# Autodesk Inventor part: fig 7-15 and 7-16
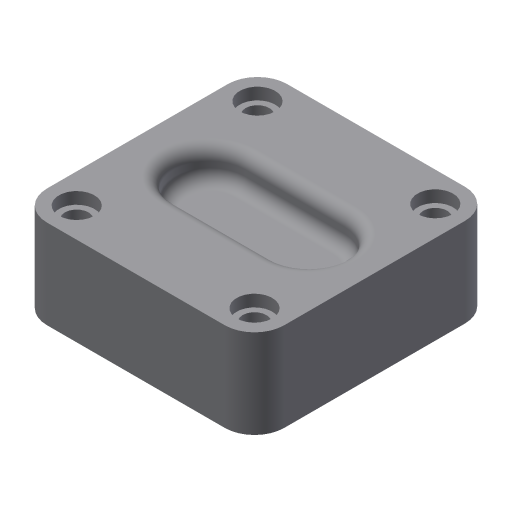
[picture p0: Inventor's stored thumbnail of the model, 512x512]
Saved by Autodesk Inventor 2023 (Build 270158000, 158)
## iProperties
Created: 2001-12
Part Number: fig 7-15 and 7-16
Document SubType Name: Modeling
Designer: Renu Muthoo
Density: 1 g/cm^3
Material: Generic
Appearance: Default
Control State: 0
Master: False
Checked Out: False
Shininess: 77.0
Angle Display Precision: 2
Document Length Units: 11269
Document Angle Units: 11279
Document Time Units: 11290
Document Mass Units: 11283
Document Length Units Precision: 3
Document Angle Units Precision: 2
Density: 0.0
Volumn: 0.0
Area: 0.0
PropertySet Name: Model Information
Author: Renu Muthoo
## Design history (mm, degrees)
sketch "Sketch1"
  geometry: L1 (-20, 20)-(20, 20); L2 (20, 20)-(20, -20.5); L3 (20, -20.5)-(-20, -20.5); L4 (-20, -20.5)-(-20, 20); 1 further point
  constraints: 8 end point, 2 parallel, 1 horizontal, 1 perpendicular, 1 other
  dimensions: "d0" = 40 distance of L1.start L1.end; "d1" = 40.5 distance of L3.end L1.start; "d100" = 20 distance from line of L4 point (0, 0); "d101" = 20 distance from line of L1 point (0, 0)
extrude "Extrusion1" new body sketch "Sketch1" distance "d2" = 15; taper "d3" = 0 deg
workplane "Work Plane1"
workplane "Work Plane2"
workplane "Work Plane3"
workplane "Work Plane4"
fillet "Fillet1" dims "d32" = 5
hole "Hole3" diameter "d66" = 4; stored, may be unused: countersink angle "d70" = 90 deg, drill point angle "d72" = 118 deg; dims "d64" = 10, "d65" = 10, "d67" = 6, "d68" = 6, "d69" = 2, "d71" = 8
hole "Hole4" diameter "d75" = 4; stored, may be unused: countersink angle "d79" = 90 deg, drill point angle "d81" = 118 deg; dims "d73" = 10, "d74" = 10, "d76" = 6, "d77" = 6, "d78" = 2, "d80" = 8
hole "Hole5" diameter "d84" = 4; stored, may be unused: countersink angle "d88" = 90 deg, drill point angle "d90" = 118 deg; dims "d82" = 10, "d83" = 10, "d85" = 6, "d86" = 6, "d87" = 2, "d89" = 8
hole "Hole6" diameter "d93" = 4; stored, may be unused: countersink angle "d97" = 90 deg, drill point angle "d99" = 118 deg; dims "d91" = 10, "d92" = 10, "d94" = 6, "d95" = 6, "d96" = 2, "d98" = 8
fillet "Fillet2" dims "d61" = 2
body "Solid1"
sketch "Sketch8"
  geometry: L1 (-9.844, 1.64)-(1.983, -10.187); L2 (10.469, -1.701)-(-1.358, 10.126); A1 r 6 centre (-5.601, 5.883) between (-1.358, 10.126) and (-9.844, 1.64); A2 r 6 centre (6.226, -5.944) between (1.983, -10.187) and (10.469, -1.701)
  constraints: 4 end point, 4 point on circle, 4 tangent, 2 centre point, 1 parallel
  dimensions: "d29" = 6 radius of A2
extrude "Extrusion2" cut sketch "Sketch8" distance "d30" = 5; taper "d31" = 0 deg
